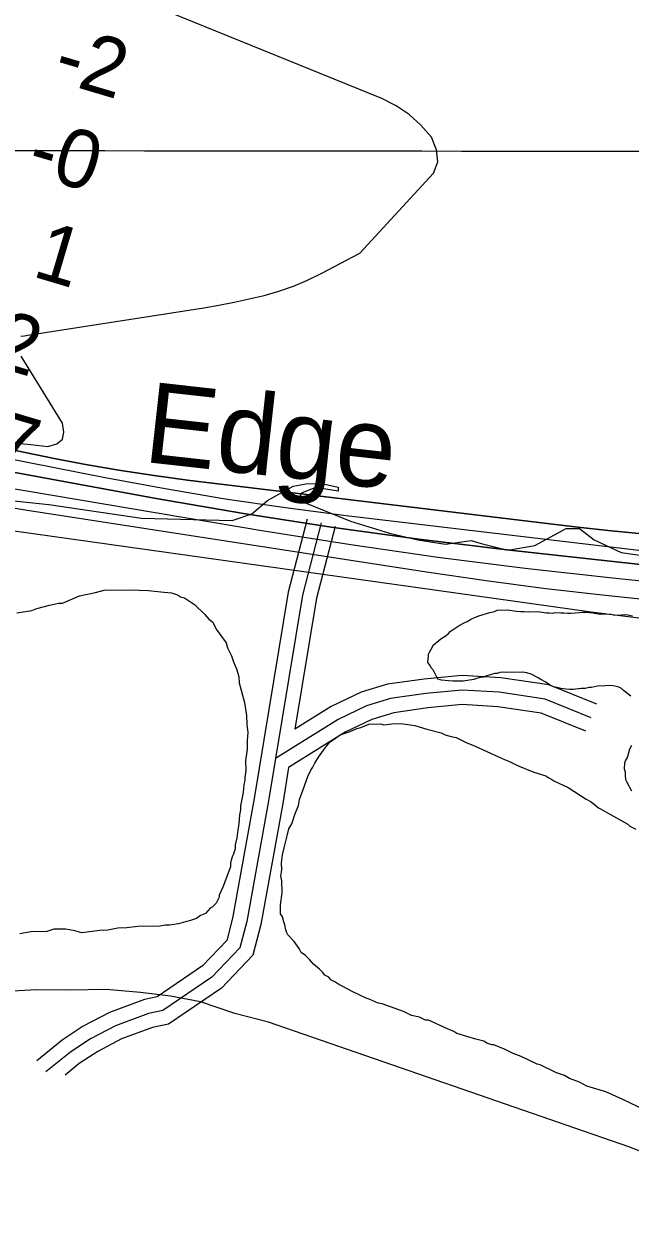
# Model space of a CAD drawing. Extents: x 3219052 to 3256913, y 800770 to 826146.
# Drawn here: x 3239388 to 3240014, y 811124 to 812354 of the extents above; entities that cross this region are included whole.
import ezdxf

# ---------------------------------------------------------------- set-up
doc = ezdxf.new("R2010")
doc.units = 0
for name, color, linetype in [('V-GRID-MAJR', 7, 'Continuous'), ('V-LEVE-TOET', 7, 'Continuous'), ('V-RIVR-EDGE', 7, 'Continuous'), ('V-RIVR-IDEN', 7, 'Continuous'), ('V-RIVR-RANG', 7, 'Continuous'), ('V-ROAD-CNTR', 7, 'Continuous'), ('V-SITE-VEGE', 7, 'Continuous'), ('V-TOPO-DPTH', 7, 'Continuous'), ('V-TOPO-MAJR', 7, 'Continuous'), ('V-TOPO-MINR', 7, 'Continuous'), ('V-TOPO-WATR', 7, 'Continuous')]:
    doc.layers.add(name, color=color, linetype=linetype)

msp = doc.modelspace()

# ---------------------------------------------------------------- linework, layer by layer
at = {"layer": 'V-GRID-MAJR'}
msp.add_spline([(3223229.222, 812245.659), (3228465.955, 812237.661), (3233702.6890000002, 812230.425), (3238939.4250000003, 812223.951), (3244176.161, 812218.238), (3249412.899, 812213.287), (3254649.637, 812209.098), (3254649.6380000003, 812209.098)], degree=3, dxfattribs=at)
at = {"layer": 'V-LEVE-TOET'}
msp.add_lwpolyline([(3240582.342, 810973.949), (3240012.289, 811195.518), (3239640.372, 811323.9770000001), (3239605.614, 811332.902), (3239570.251, 811345.123), (3239539.09, 811351.06), (3239508.235, 811354.603), (3239472.887, 811357.837), (3239436.0470000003, 811357.175), (3239400.705, 811357.415), (3239363.569, 811355.2540000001), (3239330.921, 811355.199), (3239297.078, 811353.343), (3239268.634, 811348.8030000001), (3239238.991, 811343.361), (3239077.918, 811304.15), (3238719.921, 811173.252), (3238449.923, 811076.349)], dxfattribs=at)
at = {"layer": 'V-RIVR-EDGE'}
msp.add_lwpolyline([(3239354.101284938, 811864.515829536), (3239413.636921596, 811858.2831064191), (3239509.2313631, 811844.1369949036), (3239602.6814423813, 811841.7325237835), (3239623.1284364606, 811848.6368312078), (3239639.245862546, 811862.506711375), (3239665.797674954, 811877.2201486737), (3239681.0178024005, 811879.790588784), (3239698.4037886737, 811879.3129190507), (3239712.305913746, 811876.2357887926), (3239712.2951654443, 811871.8890235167), (3239688.8323064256, 811875.8591530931), (3239674.4729333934, 811869.8091511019), (3239670.9804735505, 811863.7322783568), (3239675.755466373, 811861.1123960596), (3239724.824471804, 811840.9958199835), (3239765.219293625, 811828.7249180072), (3239794.3254236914, 811821.6980799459), (3239823.003326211, 811817.2803758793), (3239849.528267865, 811821.1268999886), (3239859.9529807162, 811818.058368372), (3239887.3204046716, 811811.0358296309), (3239915.151525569, 811815.7484823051), (3239947.7963331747, 811833.4896076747), (3239961.27130553, 811833.45628794), (3239976.4559635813, 811821.6824026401), (3240004.2430164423, 811808.5733176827), (3240042.4816529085, 811803.2626142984)], dxfattribs=at)
at = {"layer": 'V-ROAD-CNTR'}
for points in [[(3239680.1146026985, 811843.1422863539), (3239660.586641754, 811767.710437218), (3239625.43871205, 811554.987862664), (3239603.205756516, 811431.274110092), (3239597.21876849, 811408.3631559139), (3239572.1738185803, 811382.1752082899), (3239525.255912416, 811350.35527193), (3239512.247938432, 811347.6002774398), (3239476.2880103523, 811334.216304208), (3239448.871065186, 811319.8813328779), (3239427.2411084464, 811305.629361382), (3239401.1231606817, 811284.358403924)], [(3239694.6355736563, 811839.3832938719), (3239675.2766123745, 811764.6024434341), (3239640.220682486, 811552.4388677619), (3239617.865727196, 811428.0461165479), (3239610.7477414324, 811400.807171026), (3239581.912799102, 811370.656231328), (3239531.240900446, 811336.2903000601), (3239516.440930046, 811333.15530633), (3239482.4029981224, 811320.487331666), (3239456.492049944, 811306.939358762), (3239436.1260906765, 811293.5203855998), (3239410.596141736, 811272.727427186)], [(3239709.156544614, 811835.6243013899), (3239689.966582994, 811761.4944496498), (3239667.641627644, 811626.383719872)], [(3239979.14300464, 811652.0816684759), (3239929.85810321, 811672.0806284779), (3239880.17320258, 811679.43961376), (3239839.8932831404, 811681.7956090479), (3239801.102360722, 811678.1716162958), (3239763.15343662, 811672.681627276), (3239736.0264908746, 811664.6086434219), (3239704.887553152, 811649.67967328), (3239667.642627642, 811626.3827198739)], [(3239973.50301592, 811638.182696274), (3239925.8831111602, 811657.5056576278), (3239878.63320566, 811664.5036436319), (3239840.1542826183, 811666.7546391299), (3239802.8753571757, 811663.271646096), (3239766.38343016, 811657.9926566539), (3239741.4414800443, 811650.5696715), (3239712.1295386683, 811636.516699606), (3239647.425668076, 811596.0447805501)], [(3239967.8630271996, 811624.283724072), (3239921.9081191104, 811642.9306867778), (3239877.0932087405, 811649.5676735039), (3239840.415282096, 811651.7136692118), (3239804.64835363, 811648.371675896), (3239769.6134237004, 811643.3036860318), (3239746.856469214, 811636.5306995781), (3239719.3715241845, 811623.353725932), (3239661.121640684, 811586.918798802)], [(3239661.121640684, 811586.9197988), (3239655.002652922, 811549.8898728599), (3239632.5256978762, 811424.8181230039), (3239624.2767143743, 811393.2511861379), (3239591.651779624, 811359.137254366), (3239537.2258884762, 811322.2253281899), (3239520.63392166, 811318.7103352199), (3239488.5179858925, 811306.758359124), (3239464.1130347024, 811293.997384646), (3239445.011072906, 811281.411409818), (3239430.2831023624, 811269.41543381)]]:
    msp.add_lwpolyline(points, dxfattribs=at)
at = {"layer": 'V-SITE-VEGE'}
for points in [[(3239380.477, 811746.361), (3239395.909, 811748.718), (3239401.029, 811750.878), (3239414.377, 811754.2270000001), (3239423.622, 811756.4670000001), (3239427.749, 811756.545), (3239445.145, 811764.098), (3239461.59, 811767.506), (3239470.835, 811769.747), (3239497.651, 811770.257), (3239516.239, 811769.579), (3239532.781, 811767.8300000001), (3239540.02, 811766.935), (3239546.2460000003, 811764.9890000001), (3239549.382, 811762.984), (3239553.529, 811762.032), (3239563.98, 811755.007), (3239574.49, 811744.888), (3239578.715, 811739.809), (3239582.899, 811736.794), (3239586.131, 811729.632), (3239596.719, 811715.389), (3239597.85, 811710.25), (3239602.134, 811702.079), (3239604.313, 811695.929), (3239607.563, 811687.735), (3239609.767, 811680.554), (3239609.882, 811674.367), (3239615.43, 811653.834), (3239617.75, 811640.465), (3239617.926, 811631.181), (3239619.114, 811622.948), (3239618.239, 811614.676), (3239618.416, 811605.395), (3239616.568, 811594.01), (3239616.765, 811583.694), (3239615.872, 811576.454), (3239615.929, 811573.36), (3239614.977, 811569.215), (3239614.103, 811560.943), (3239611.264, 811547.475), (3239611.342, 811543.348), (3239610.4080000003, 811538.171), (3239609.554, 811528.8690000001), (3239608.6380000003, 811522.662), (3239607.764, 811514.39), (3239605.839, 811507.13), (3239605.917, 811503.005), (3239603.971, 811496.777), (3239602.98, 811494.694), (3239601.034, 811488.466), (3239601.112, 811484.339), (3239593.254, 811463.552), (3239589.285, 811455.223), (3239589.324, 811453.161), (3239586.346, 811446.912), (3239582.299, 811442.708), (3239580.255, 811441.639), (3239575.197, 811436.381), (3239570.079, 811434.219), (3239566.011, 811431.0480000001), (3239559.861, 811428.867), (3239554.725, 811427.7390000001), (3239547.543, 811425.537), (3239538.279, 811424.331), (3239534.1550000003, 811424.251), (3239527.984, 811423.1020000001), (3239505.292, 811422.67), (3239493.967, 811421.425), (3239484.681, 811421.247), (3239474.406, 811418.988), (3239466.1550000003, 811418.834), (3239447.629, 811416.415), (3239440.369, 811418.341), (3239431.046, 811420.229), (3239418.668, 811419.991), (3239411.49, 811417.792), (3239394.985, 811417.478), (3239383.678, 811415.201)], [(3239807.239, 811692.0210000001), (3239804.802, 811695.2980000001), (3239805.2060000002, 811699.105), (3239805.636, 811701.487), (3239805.591, 811703.86), (3239806.504, 811705.777), (3239809.261, 811710.578), (3239810.164, 811712.97), (3239818.108, 811719.767), (3239823.74, 811723.198), (3239826.077, 811725.1410000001), (3239827.938, 811727.077), (3239837.3140000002, 811733.427), (3239842.9560000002, 811736.383), (3239845.311, 811737.378), (3239850.003, 811740.317), (3239853.299, 811741.804), (3239857.546, 811743.307), (3239868.872, 811746.848), (3239873.6010000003, 811747.886), (3239876.423, 811749.363), (3239887.338, 811749.572), (3239895.909, 811748.31), (3239900.667, 811747.925), (3239903.987, 811747.9890000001), (3239908.267, 811747.596), (3239918.235, 811747.786), (3239924.899, 811746.963), (3239927.281, 811746.533), (3239930.129, 811746.588), (3239933.935, 811746.184), (3239936.298, 811746.7050000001), (3239942.004, 811746.338), (3239945.326, 811746.402), (3239949.133, 811745.998), (3239952.455, 811746.062), (3239961.464, 811746.709), (3239964.3000000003, 811747.237), (3239967.151, 811747.29), (3239971.431, 811746.897), (3239974.278, 811746.952), (3239976.67, 811746.047), (3239983.3340000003, 811745.224), (3239989.505, 811745.343), (3239993.785, 811744.947), (3239996.167, 811744.519), (3240001.873, 811744.153), (3240007.558, 811744.734), (3240011.365, 811744.333), (3240016.129, 811743.475)], [(3240014.386, 811660.349), (3240006.673, 811666.372), (3240004.74, 811668.238), (3240001.865, 811669.606), (3239998.039, 811670.957), (3239994.234, 811671.361), (3239988.063, 811671.2440000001), (3239980.004, 811670.615), (3239973.852, 811669.5480000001), (3239971.4790000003, 811669.503), (3239967.223, 811668.473), (3239962.953, 811668.3910000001), (3239954.9020000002, 811667.289), (3239951.105, 811667.218), (3239947.3000000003, 811667.6190000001), (3239942.059, 811668.469), (3239939.677, 811668.899), (3239934.428, 811670.224), (3239930.596, 811672.051), (3239926.744, 811674.826), (3239921.468, 811677.574), (3239918.585, 811679.42), (3239911.392, 811683.079), (3239907.096, 811684.4230000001), (3239902.805, 811685.291), (3239885.719, 811684.966), (3239882.864, 811685.388), (3239879.073, 811684.841), (3239876.24, 811683.837), (3239873.8710000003, 811683.792), (3239866.787, 811681.758), (3239862.066, 811680.243), (3239858.753, 811679.706), (3239854.974, 811678.684), (3239852.144, 811677.681), (3239841.254, 811676.049), (3239830.812, 811675.8520000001), (3239826.056, 811676.235), (3239818.919, 811677.0480000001), (3239815.103, 811677.927), (3239810.168, 811687.802), (3239808.232, 811689.666), (3239807.239, 811692.0210000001)], [(3239759.484, 811630.792), (3239767.717, 811631.98), (3239777, 811632.156), (3239791.48, 811630.368), (3239803.936, 811626.4770000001), (3239818.454, 811622.6290000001), (3239822.62, 811620.64), (3239828.848, 811618.696), (3239834.025, 811617.763), (3239844.437, 811612.8), (3239853.798, 811608.8520000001), (3239877.737, 811597.956), (3239883.986, 811594.981), (3239889.182, 811593.017), (3239897.5130000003, 811589.045), (3239914.153, 811582.14), (3239926.607, 811578.248), (3239929.742, 811576.245), (3239931.825, 811575.252), (3239934.961, 811573.2490000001), (3239949.536, 811566.302), (3239968.339, 811554.277), (3239973.555, 811551.282), (3239980.893, 811545.231), (3239982.9760000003, 811544.237), (3239990.273, 811540.25), (3240011.1380000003, 811528.265), (3240013.241, 811526.2390000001), (3240019.49, 811523.2660000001)], [(3240029.126, 811233.496), (3240006.217, 811244.414), (3239988.524, 811252.334), (3239968.81, 811258.148), (3239961.511, 811262.138), (3239951.117, 811266.068), (3239945.901, 811269.064), (3239937.59, 811272.001), (3239920.93, 811279.939), (3239917.8170000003, 811280.912), (3239901.156, 811288.85), (3239892.846, 811291.786), (3239884.514, 811295.756), (3239873.0700000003, 811300.697), (3239871.008, 811300.658), (3239865.812, 811302.62), (3239862.679, 811304.627), (3239854.386, 811306.534), (3239845.045, 811309.453), (3239834.67, 811312.35), (3239831.539, 811314.353), (3239825.29, 811317.331), (3239805.517, 811326.242), (3239802.42, 811326.183), (3239796.1720000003, 811329.158), (3239787.886, 811331.0650000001), (3239779.552, 811335.034), (3239757.737, 811342.8740000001), (3239753.592, 811343.826), (3239744.228, 811347.777), (3239741.113, 811348.75), (3239726.536, 811355.694), (3239711.938, 811363.671), (3239708.804, 811365.676), (3239704.6410000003, 811367.6630000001), (3239702.519, 811370.716), (3239698.353, 811372.699), (3239696.231, 811375.757), (3239693.078, 811378.792), (3239686.79, 811383.832), (3239682.5670000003, 811388.911), (3239678.363, 811392.958), (3239674.177, 811395.9720000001), (3239672.036, 811400.06), (3239666.742, 811407.181), (3239660.416, 811414.286), (3239659.345, 811416.329), (3239658.255, 811419.404), (3239657.125, 811424.542), (3239656.035, 811427.616), (3239654.907, 811432.752), (3239652.7830000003, 811435.808), (3239652.607, 811445.0920000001), (3239654.438, 811457.509), (3239654.2, 811469.885), (3239653.0700000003, 811475.023), (3239653.983, 811481.233), (3239653.846, 811488.452), (3239654.721, 811496.726), (3239656.648, 811503.984), (3239659.505, 811516.419), (3239661.432, 811523.679), (3239664.428, 811528.8960000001), (3239665.401, 811532.009), (3239667.346, 811538.237), (3239671.295, 811547.6), (3239672.208, 811553.808), (3239676.1380000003, 811564.201), (3239681.041, 811577.708), (3239684.017, 811583.954), (3239686.022, 811587.09), (3239688.007, 811591.253), (3239692.015, 811597.52), (3239697.034, 811604.84), (3239700.051, 811609.024), (3239704.098, 811613.228), (3239707.153, 811615.3520000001), (3239714.276, 811620.644), (3239717.35, 811621.736), (3239721.457, 811622.846), (3239724.5330000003, 811623.935), (3239731.693, 811627.167), (3239735.799, 811628.277), (3239743.9930000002, 811631.529), (3239756.3710000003, 811631.765), (3239759.484, 811630.792)], [(3240015.293, 811562.555), (3240010.3680000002, 811571.957), (3240009.375, 811574.31), (3240008.809, 811579.049), (3240008.754, 811581.898), (3240007.742, 811585.203), (3240008.091, 811591.855), (3240009.002, 811593.772), (3240010.839, 811597.1290000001), (3240013.5160000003, 811606.204), (3240015.343, 811610.035)]]:
    msp.add_lwpolyline(points, dxfattribs=at)
at = {"layer": 'V-TOPO-DPTH'}
for points in [[(3240769.033000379, 811768.2023254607), (3240559.2751383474, 811767.5806693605), (3240495.7296046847, 811767.8835352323), (3240432.1989980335, 811768.8410095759), (3240368.6907819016, 811770.7803966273), (3240305.19749278, 811773.3743921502), (3240200.543008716, 811778.4605902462), (3240189.3961591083, 811779.1039135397), (3240178.2599627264, 811779.8820655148), (3240167.13974618, 811780.8624605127), (3240156.0301828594, 811781.9776841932), (3239886.468029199, 811811.5141871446), (3239795.617629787, 811822.4610473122), (3239704.9572357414, 811834.708582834), (3239614.581849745, 811848.907131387), (3239524.3964691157, 811864.4063552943), (3239376.739947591, 811891.4241558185), (3239360.542982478, 811894.4778513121), (3239344.36934104, 811897.6472704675), (3239328.2306851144, 811900.990275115), (3239312.1153528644, 811904.4490034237), (3238520.5956911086, 811925.9982919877)], [(3240022.580886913, 811828.2235354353), (3239991.0516646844, 811831.4089095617), (3239959.5524673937, 811834.8786404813), (3239928.073286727, 811838.5379425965), (3239556.690266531, 811883.4085199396), (3239522.163457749, 811888.0068470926), (3239487.7270374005, 811893.1625289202), (3239453.4261997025, 811899.1542427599), (3239419.215750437, 811905.7033112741), (3239360.4583122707, 811917.6942584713)], [(3239360.4583122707, 811917.6942584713), (3239419.215750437, 811905.7033112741), (3239453.4261997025, 811899.1542427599), (3239487.7270374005, 811893.1625289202), (3239522.163457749, 811888.0068470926), (3239556.690266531, 811883.4085199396), (3239928.073286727, 811838.5379425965), (3239959.5524673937, 811834.8786404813), (3239991.0516646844, 811831.4089095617), (3240022.580886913, 811828.2235354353)]]:
    msp.add_lwpolyline(points, dxfattribs=at)
at = {"layer": 'V-TOPO-MAJR'}
msp.add_lwpolyline([(3238434.7078639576, 811837.7319492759), (3239311.6855875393, 811840.4262749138), (3239317.627886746, 811839.4776945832), (3239322.1585456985, 811838.7679730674), (3239326.691839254, 811838.0758509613), (3239331.2290847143, 811837.4101279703), (3239335.768964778, 811836.7620043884), (3239973.3219053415, 811747.6361044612), (3240006.2451086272, 811743.2760959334), (3240039.2049762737, 811739.2340704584), (3240072.2198404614, 811735.6690195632), (3240105.27136901, 811732.421951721), (3240138.3656815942, 811729.6370141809), (3240171.4803488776, 811727.1499879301), (3240204.6255482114, 811725.1098286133), (3240237.7911022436, 811723.367580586), (3240397.165473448, 811716.0728522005), (3240465.615937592, 811712.9142279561), (3240534.064801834, 811709.7215752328), (3240602.511266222, 811706.4778797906), (3240670.9561307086, 811703.2001558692)], dxfattribs=at)
at = {"layer": 'V-TOPO-MINR'}
for points in [[(3239384.798820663, 812031.8399047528), (3239388.4025208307, 812032.3091784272), (3239391.9999087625, 812032.831484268), (3239573.443667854, 812061.2211319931), (3239589.133152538, 812063.9011223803), (3239604.7632470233, 812066.871452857), (3239620.3042562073, 812070.2772934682), (3239635.7858751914, 812073.9734741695), (3239651.0196776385, 812078.4173749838), (3239665.9856830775, 812083.5592199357), (3239680.549993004, 812089.7479810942), (3239694.846505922, 812096.6346863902), (3239734.661690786, 812117.5864869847), (3239810.7702009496, 812199.9219792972), (3239815.2164787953, 812211.704691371), (3239813.834515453, 812224.2223536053), (3239808.567057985, 812237.2299826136), (3239797.654294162, 812249.6997184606), (3239785.6352867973, 812260.74472152), (3239771.9569141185, 812269.6526253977), (3239757.1722978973, 812277.1357964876), (3239512.869969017, 812376.0645267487)], [(3237025.2740428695, 812089.4185243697), (3238493.201968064, 811953.2482152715), (3238517.201058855, 811946.7728898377), (3239329.4793078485, 811914.9830428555), (3239338.858920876, 811912.7954531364), (3239348.2552308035, 811910.6843577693), (3239357.676586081, 811908.6880039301), (3239367.114638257, 811906.7681444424), (3239471.7874726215, 811886.1397889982), (3239533.6872031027, 811874.678702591), (3239595.737061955, 811864.1705298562), (3239658.0121133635, 811855.0917276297), (3239720.437293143, 811846.9658390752), (3240170.7075255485, 811793.6118011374), (3240175.304957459, 811793.1094056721), (3240179.907297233, 811792.6628783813), (3240184.516998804, 811792.3001533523), (3240189.13160824, 811791.9932964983), (3240238.2444342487, 811789.1759900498), (3240267.426285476, 811787.77521553), (3240296.6176557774, 811786.7378840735), (3240325.82330469, 811786.2457172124), (3240355.0384726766, 811786.1169934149), (3240791.40437533, 811788.2684641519)], [(3236943.0259246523, 812035.7495556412), (3238400.420479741, 811879.8452404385), (3238429.331135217, 811875.239076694), (3239333.6498527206, 811861.6271375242), (3239361.4474915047, 811857.0846881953), (3239389.268618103, 811852.682627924), (3239803.3859657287, 811788.7659327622), (3239864.9200130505, 811779.8268367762), (3239926.5447105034, 811771.6176601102), (3239988.3053831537, 811764.5033624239), (3240050.156705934, 811758.118984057), (3240118.536101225, 811751.673519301), (3240146.281664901, 811749.3061256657), (3240174.0484149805, 811747.2670447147), (3240201.846944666, 811745.7204327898), (3240229.6666607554, 811744.5021335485), (3240678.498516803, 811728.8310884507)], [(3239380.8678811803, 811921.7747939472), (3239387.8562084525, 811920.8193848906), (3239394.8659087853, 811920.004457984), (3239412.662471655, 811918.2076632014), (3239421.641505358, 811920.9427674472), (3239427.634567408, 811925.5450548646), (3239429.148671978, 811932.9481170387), (3239427.676804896, 811942.2183623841), (3239384.9748514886, 812011.2826220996)], [(3238464.5131107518, 811917.3194546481), (3239339.5213585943, 811881.3794800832), (3239364.138784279, 811876.9531903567), (3239388.784066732, 811872.677838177), (3239635.641490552, 811831.0235593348), (3239725.329712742, 811816.8013555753), (3239815.1782088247, 811803.7665068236), (3239905.267115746, 811792.5126905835), (3239995.51629656, 811782.4462293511), (3240138.5381635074, 811767.9253425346), (3240157.408869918, 811766.1810402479), (3240176.2957569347, 811764.6637556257), (3240195.2069148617, 811763.4869975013), (3240214.134253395, 811762.5372570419), (3240454.1963994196, 811752.6588328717), (3240514.046581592, 811750.5723415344), (3240573.906888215, 811748.9869978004), (3240633.782381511, 811748.1533754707), (3240693.6679992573, 811747.8209007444)], [(3238520.5956911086, 811925.9982919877), (3239312.1153528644, 811904.4490034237), (3239328.2306851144, 811900.990275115), (3239344.36934104, 811897.6472704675), (3239360.542982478, 811894.4778513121), (3239376.739947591, 811891.4241558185), (3239524.3964691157, 811864.4063552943), (3239614.581849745, 811848.907131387), (3239704.9572357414, 811834.708582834), (3239795.617629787, 811822.4610473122), (3239886.468029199, 811811.5141871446), (3240156.0301828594, 811781.9776841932), (3240167.13974618, 811780.8624605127), (3240178.2599627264, 811779.8820655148), (3240189.3961591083, 811779.1039135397), (3240200.543008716, 811778.4605902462), (3240305.19749278, 811773.3743921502), (3240368.6907819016, 811770.7803966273), (3240432.1989980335, 811768.8410095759), (3240495.7296046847, 811767.8835352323), (3240559.2751383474, 811767.5806693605), (3240769.033000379, 811768.2023254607)]]:
    msp.add_lwpolyline(points, dxfattribs=at)
at = {"layer": 'V-TOPO-WATR'}
msp.add_lwpolyline([(3239360.4583122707, 811917.6942584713), (3239419.215750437, 811905.7033112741), (3239453.4261997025, 811899.1542427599), (3239487.7270374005, 811893.1625289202), (3239522.163457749, 811888.0068470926), (3239556.690266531, 811883.4085199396), (3239928.073286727, 811838.5379425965), (3239959.5524673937, 811834.8786404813), (3239991.0516646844, 811831.4089095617), (3240022.580886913, 811828.2235354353)], dxfattribs=at)

# ---------------------------------------------------------------- texts
at = {"layer": 'V-RIVR-IDEN'}
msp.add_text(' Edge', height=83.00000000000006, rotation=353.65980825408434, dxfattribs=at).set_placement((3239479.308522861, 811905.7801028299))
at = {"layer": 'V-RIVR-RANG'}
for s, p in [('-2', (3239415.759142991, 812296.5150215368)), ('-0', (3239388.6050986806, 812200.2627244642)), ('1', (3239395.188968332, 812093.977532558)), ('2', (3239352.1853671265, 812002.4382062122)), ('0.7', (3239285.4074305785, 811917.9673359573))]:
    msp.add_text(s, height=60, rotation=343.4398055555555, dxfattribs=at).set_placement(p)

doc.saveas('drawing.dxf')
